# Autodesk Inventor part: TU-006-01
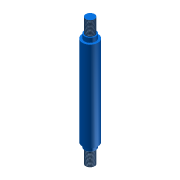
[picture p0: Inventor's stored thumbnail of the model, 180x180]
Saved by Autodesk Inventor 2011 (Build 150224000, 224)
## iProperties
Shininess: 64.0
Angle Display Precision: 2
Document Length Units: 11269
Document Angle Units: 11279
Document Time Units: 11290
Document Mass Units: 11286
Document Length Units Precision: 3
Document Angle Units Precision: 2
Compacted: True
Created: 2002-07
Part Number: TU-006-01
Document SubType Name: Modeling
Designer: PN
Description: Piston Rod - 35 mm stroke
Density: 8.08 g/cm^3
Mass: 144.065 g
Surface Area: 58.412 cm^2
Volume: 17.8299 cm^3
Material: Stainless Steel
Density: 0.0
Volumn: 0.0
Area: 0.0
PropertySet Name: Model Information
Control State: 0
Master: False
Checked Out: False
Stroke_Length: 35.000 mm
Author: PN
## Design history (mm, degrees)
sketch "Sketch1"
  geometry: L1 (0, 115)-(4, 115); L2 (4, 0)-(0, 0); L3 (7, 98)-(7, 17); L4 (5, 98)-(7, 98); L5 (5, 102)-(5, 98); L6 (4, 102)-(5, 102); L7 (4, 115)-(4, 102); L8 (0, 115)-(0, 0); L9 (4, 0)-(4, 13); L10 (4, 13)-(5, 13); L11 (5, 13)-(5, 17); L12 (5, 17)-(7, 17); 1 further point
  constraints: 24 end point, 7 parallel, 3 perpendicular, 2 collinear, 1 coincident, 1 vertical
  dimensions: "d11" = 14 diameter of L3 L8; "d15" = 115 distance between parallel lines of L2 L1 (computed from Stroke_Length); "d16" = 8 diameter of L7 L8; "d17" = 10 diameter of L5 L8; "d32" = 13 distance of L2.start L9.end; "d33" = 4 distance of L10.end L11.end; "d36" = 81 distance between parallel lines of L4 L12 (computed from Stroke_Length); "d38" = 4 distance of L5.start L4.start
revolve "Revolution1" sketch "Sketch1" stored, may be unused: angle "d0" = 90 deg
thread "Thread3" dims "d34" = 10, "d35" = 0
body "Solid1"
thread "Thread1" dims "d23" = 10, "d24" = 0
other parameters: "Stroke_Length" = 35 [user parameter; used in 2 equation terms]
